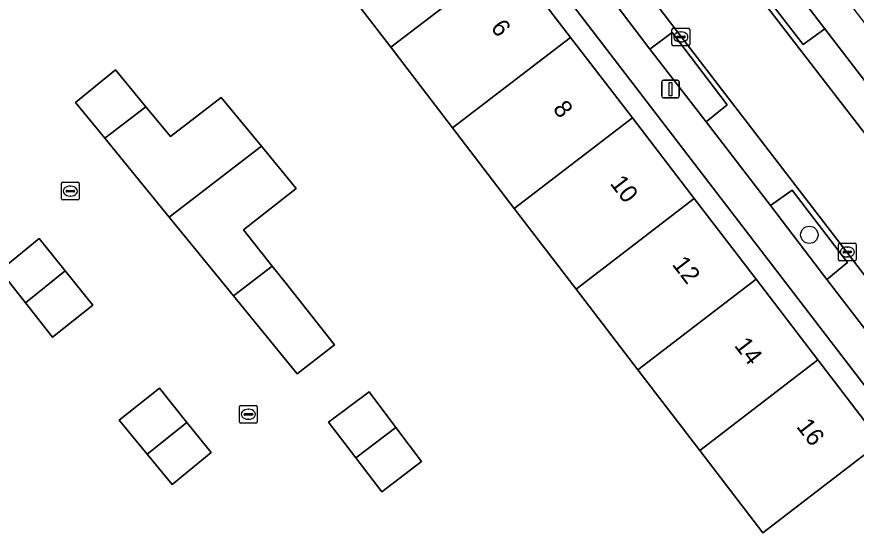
# Model space of a CAD drawing. Extents: x 161771 to 163125, y 382475 to 383179.
# Drawn here: x 162117.97 to 162165.3, y 382952.28 to 382981.52 of the extents above; entities that cross this region are included whole.
import ezdxf

# ---------------------------------------------------------------- set-up
doc = ezdxf.new("R2010")
doc.units = 0
for name, color, linetype in [('IMGEO_Boom', 7, 'Continuous'), ('IMGEO_Erf', 7, 'Continuous'), ('IMGEO_Groenvoorziening', 7, 'Continuous'), ('IMGEO_Kolk', 7, 'Continuous'), ('IMGEO_Lichtmast', 7, 'Continuous'), ('IMGEO_Pand', 7, 'Continuous'), ('IMGEO_Pand_nummerreeks', 7, 'Continuous'), ('IMGEO_Parkeervlak_open', 7, 'Continuous'), ('IMGEO_Rijbaan_lokaal_open', 7, 'Continuous'), ('IMGEO_Voetpad_open', 7, 'Continuous')]:
    doc.layers.add(name, color=color, linetype=linetype)

msp = doc.modelspace()

# ---------------------------------------------------------------- linework, layer by layer
at = {"layer": 'IMGEO_Boom'}
msp.add_circle((162162.658, 382969.221), 0.489, dxfattribs=at)
at = {"layer": 'IMGEO_Erf'}
for points in [[(162171.315, 382953.515), (162139.621, 382994.827)], [(162145.708, 382984.903), (162149.193, 382980.357), (162152.679, 382975.81), (162156.165, 382971.263), (162159.651, 382966.716), (162163.136, 382962.17), (162166.694, 382957.529), (162162.721, 382954.48), (162160.035, 382952.419), (162156.476, 382957.064), (162152.992, 382961.611), (162149.507, 382966.159), (162146.023, 382970.706), (162142.538, 382975.255), (162139.054, 382979.802), (162135.57, 382984.35)]]:
    msp.add_lwpolyline(points, dxfattribs=at)
for points in [[(162130.186, 382965.785), (162126.562, 382970.226), (162122.938, 382974.667), (162121.291, 382976.685), (162123.543, 382978.523), (162125.253, 382976.442), (162126.629, 382974.767), (162129.497, 382976.965), (162131.764, 382974.213), (162133.719, 382971.841), (162130.749, 382969.511), (162132.372, 382967.462), (162133.078, 382966.57), (162135.892, 382963.014), (162133.777, 382961.385)], [(162122.254, 382965.25), (162119.988, 382963.442), (162118.457, 382965.388), (162117.027, 382967.206), (162119.234, 382969.014), (162120.702, 382967.184)], [(162128.923, 382956.94), (162126.723, 382955.139), (162125.318, 382956.855), (162123.753, 382958.768), (162126.01, 382960.571), (162127.555, 382958.645)], [(162135.543, 382958.656), (162137.841, 382960.372), (162139.34, 382958.365), (162140.783, 382956.433), (162138.555, 382954.726), (162137.089, 382956.639)]]:
    msp.add_lwpolyline(points, close=True, dxfattribs=at)
at = {"layer": 'IMGEO_Groenvoorziening'}
for points in [[(162163.535, 382980.839), (162160.363, 382984.984), (162159.193, 382984.002), (162162.318, 382979.963)], [(162156.849, 382975.589), (162158.024, 382976.553), (162154.92, 382980.631), (162153.663, 382979.7)], [(162163.651, 382966.699), (162164.818, 382967.667), (162161.693, 382971.745), (162160.476, 382970.878)]]:
    msp.add_lwpolyline(points, close=True, dxfattribs=at)
at = {"layer": 'IMGEO_Kolk'}
for p, q in [((162154.912, 382979.955), (162154.912, 382980.807)), ((162154.987, 382980.881), (162155.839, 382980.881)), ((162155.913, 382980.807), (162155.913, 382979.955)), ((162155.171, 382980.375), (162155.171, 382980.387)), ((162155.609, 382980.338), (162155.211, 382980.338)), ((162155.214, 382980.424), (162155.612, 382980.424)), ((162155.4, 382980.661), (162155.425, 382980.661)), ((162155.655, 382980.387), (162155.655, 382980.375)), ((162155.839, 382979.881), (162154.987, 382979.881)), ((162155.423, 382980.101), (162155.398, 382980.101)), ((162120.492, 382971.26), (162120.492, 382972.112)), ((162120.567, 382972.186), (162121.419, 382972.186)), ((162120.98, 382971.966), (162121.005, 382971.966)), ((162121.493, 382972.112), (162121.493, 382971.26)), ((162120.751, 382971.68), (162120.751, 382971.692)), ((162121.189, 382971.643), (162120.791, 382971.643)), ((162120.794, 382971.729), (162121.192, 382971.729)), ((162121.003, 382971.406), (162120.978, 382971.406)), ((162121.235, 382971.692), (162121.235, 382971.68)), ((162121.419, 382971.186), (162120.567, 382971.186)), ((162164.299, 382967.828), (162164.299, 382968.68)), ((162164.374, 382968.754), (162165.226, 382968.754)), ((162164.787, 382968.534), (162164.812, 382968.534)), ((162165.3, 382968.68), (162165.3, 382967.828)), ((162164.558, 382968.248), (162164.558, 382968.26)), ((162164.996, 382968.211), (162164.598, 382968.211)), ((162164.601, 382968.297), (162164.999, 382968.297)), ((162165.042, 382968.26), (162165.042, 382968.248)), ((162165.226, 382967.754), (162164.374, 382967.754)), ((162164.81, 382967.974), (162164.785, 382967.974)), ((162130.529, 382958.676), (162130.529, 382959.528)), ((162130.604, 382959.602), (162131.456, 382959.602)), ((162131.53, 382959.528), (162131.53, 382958.676)), ((162130.788, 382959.096), (162130.788, 382959.108)), ((162131.226, 382959.059), (162130.828, 382959.059)), ((162130.831, 382959.145), (162131.229, 382959.145)), ((162131.017, 382959.382), (162131.042, 382959.382)), ((162131.272, 382959.108), (162131.272, 382959.096)), ((162131.456, 382958.602), (162130.604, 382958.602)), ((162131.04, 382958.822), (162131.015, 382958.822))]:
    msp.add_line(p, q, dxfattribs=at)
for points in [[(162154.912, 382979.955), (162154.912, 382980.807)], [(162154.987, 382980.881), (162155.839, 382980.881)], [(162155.913, 382980.807), (162155.913, 382979.955)], [(162155.839, 382979.881), (162154.987, 382979.881)], [(162120.492, 382971.26), (162120.492, 382972.112)], [(162120.567, 382972.186), (162121.419, 382972.186)], [(162121.493, 382972.112), (162121.493, 382971.26)], [(162121.419, 382971.186), (162120.567, 382971.186)], [(162164.299, 382967.828), (162164.299, 382968.68)], [(162164.374, 382968.754), (162165.226, 382968.754)], [(162165.3, 382968.68), (162165.3, 382967.828)], [(162165.226, 382967.754), (162164.374, 382967.754)], [(162130.529, 382958.676), (162130.529, 382959.528)], [(162130.604, 382959.602), (162131.456, 382959.602)], [(162131.53, 382959.528), (162131.53, 382958.676)], [(162131.456, 382958.602), (162130.604, 382958.602)]]:
    msp.add_lwpolyline(points, dxfattribs=at)
for centre, radius, start, end in [((162154.989, 382980.805), 0.0765, 91.552, 178.448), ((162154.989, 382980.805), 0.0765, 91.552, 178.448), ((162155.837, 382980.805), 0.0765, 1.552, 88.448), ((162155.837, 382980.805), 0.0765, 1.552, 88.448), ((162155.211, 382980.384), 0.0403, 85.8775, 175.7526), ((162155.208, 382980.374), 0.0366, 178.938, 274.7102), ((162155.612, 382980.381), 0.043, 264.8664, 352.4533), ((162155.616, 382980.386), 0.0386, 1.7309, 96.639), ((162154.989, 382979.957), 0.0765, 181.552, 268.448), ((162154.989, 382979.957), 0.0765, 181.552, 268.448), ((162155.837, 382979.957), 0.0765, 271.552, 358.448), ((162155.837, 382979.957), 0.0765, 271.552, 358.448), ((162120.569, 382972.11), 0.0765, 91.552, 178.448), ((162120.569, 382972.11), 0.0765, 91.552, 178.448), ((162121.417, 382972.11), 0.0765, 1.552, 88.448), ((162121.417, 382972.11), 0.0765, 1.552, 88.448), ((162120.791, 382971.689), 0.0403, 85.8775, 175.7526), ((162120.788, 382971.679), 0.0366, 178.938, 274.7102), ((162121.192, 382971.686), 0.043, 264.8664, 352.4533), ((162121.196, 382971.691), 0.0386, 1.7309, 96.639), ((162120.569, 382971.262), 0.0765, 181.552, 268.448), ((162120.569, 382971.262), 0.0765, 181.552, 268.448), ((162121.417, 382971.262), 0.0765, 271.552, 358.448), ((162121.417, 382971.262), 0.0765, 271.552, 358.448), ((162164.376, 382968.678), 0.0765, 91.552, 178.448), ((162164.376, 382968.678), 0.0765, 91.552, 178.448), ((162165.224, 382968.678), 0.0765, 1.552, 88.448), ((162165.224, 382968.678), 0.0765, 1.552, 88.448), ((162164.598, 382968.257), 0.0403, 85.8775, 175.7526), ((162164.595, 382968.247), 0.0366, 178.938, 274.7102), ((162164.999, 382968.254), 0.043, 264.8664, 352.4533), ((162165.003, 382968.259), 0.0386, 1.7309, 96.639), ((162164.376, 382967.83), 0.0765, 181.552, 268.448), ((162164.376, 382967.83), 0.0765, 181.552, 268.448), ((162165.224, 382967.83), 0.0765, 271.552, 358.448), ((162165.224, 382967.83), 0.0765, 271.552, 358.448), ((162130.606, 382959.526), 0.0765, 91.552, 178.448), ((162130.606, 382959.526), 0.0765, 91.552, 178.448), ((162131.454, 382959.526), 0.0765, 1.552, 88.448), ((162131.454, 382959.526), 0.0765, 1.552, 88.448), ((162130.828, 382959.105), 0.0403, 85.8775, 175.7526), ((162130.825, 382959.095), 0.0366, 178.938, 274.7102), ((162131.229, 382959.102), 0.043, 264.8664, 352.4533), ((162131.233, 382959.107), 0.0386, 1.7309, 96.639), ((162130.606, 382958.678), 0.0765, 181.552, 268.448), ((162130.606, 382958.678), 0.0765, 181.552, 268.448), ((162131.454, 382958.678), 0.0765, 271.552, 358.448), ((162131.454, 382958.678), 0.0765, 271.552, 358.448)]:
    msp.add_arc(centre, radius, start, end, dxfattribs=at)
for centre, major_axis, ratio, start_param, end_param in [((162155.399, 382980.381), (-0.387, 0.002), 0.722429, 4.712389, 7.853982), ((162155.424, 382980.381), (-0.39, 0.002), 0.717154, 1.570796, 4.712389), ((162120.979, 382971.686), (-0.387, 0.002), 0.722429, 4.712389, 7.853982), ((162121.004, 382971.686), (-0.39, 0.002), 0.717154, 1.570796, 4.712389), ((162164.786, 382968.254), (-0.387, 0.002), 0.722429, 4.712389, 7.853982), ((162164.811, 382968.254), (-0.39, 0.002), 0.717154, 1.570796, 4.712389), ((162131.016, 382959.102), (-0.387, 0.002), 0.722429, 4.712389, 7.853982), ((162131.041, 382959.102), (-0.39, 0.002), 0.717154, 1.570796, 4.712389)]:
    msp.add_ellipse(centre, major_axis=major_axis, ratio=ratio, start_param=start_param, end_param=end_param, dxfattribs=at)
at = {"layer": 'IMGEO_Lichtmast'}
for p, q in [((162154.437, 382977.94), (162155.227, 382977.94)), ((162155.227, 382977.94), (162154.437, 382977.94)), ((162154.337, 382977.04), (162154.337, 382977.84)), ((162154.337, 382977.84), (162154.337, 382977.04)), ((162155.327, 382977.84), (162155.327, 382977.04)), ((162155.327, 382977.04), (162155.327, 382977.84)), ((162155.227, 382976.94), (162154.437, 382976.94)), ((162154.437, 382976.94), (162155.227, 382976.94))]:
    msp.add_line(p, q, dxfattribs=at)
msp.add_lwpolyline([(162154.757, 382977.815), (162154.907, 382977.815), (162154.907, 382977.065), (162154.757, 382977.065), (162154.757, 382977.815)], dxfattribs=at)
for centre, start, end in [((162154.437, 382977.84), 90, 180), ((162154.437, 382977.84), 90, 180), ((162155.227, 382977.84), 0, 90), ((162155.227, 382977.84), 360, 90), ((162154.437, 382977.04), 180, 270), ((162154.437, 382977.04), 180, 270), ((162155.227, 382977.04), 270, 0), ((162155.227, 382977.04), 270, 0)]:
    msp.add_arc(centre, 0.1, start, end, dxfattribs=at)
at = {"layer": 'IMGEO_Pand'}
for points in [[(162135.57, 382984.35), (162139.054, 382979.802), (162145.708, 382984.903), (162142.222, 382989.449)], [(162142.538, 382975.255), (162149.193, 382980.357), (162145.708, 382984.903), (162139.054, 382979.802)], [(162146.023, 382970.706), (162152.679, 382975.81), (162149.193, 382980.357), (162142.538, 382975.255)], [(162122.938, 382974.667), (162125.253, 382976.442), (162123.543, 382978.523), (162121.291, 382976.685)], [(162122.938, 382974.667), (162126.562, 382970.226), (162131.764, 382974.213), (162129.497, 382976.965), (162126.629, 382974.767), (162125.253, 382976.442)], [(162146.023, 382970.706), (162149.507, 382966.159), (162156.165, 382971.263), (162152.679, 382975.81)], [(162132.372, 382967.462), (162130.749, 382969.511), (162133.719, 382971.841), (162131.764, 382974.213), (162126.562, 382970.226), (162130.186, 382965.785)], [(162152.992, 382961.611), (162159.651, 382966.716), (162156.165, 382971.263), (162149.507, 382966.159)], [(162118.457, 382965.388), (162120.702, 382967.184), (162119.234, 382969.014), (162117.027, 382967.206)], [(162118.457, 382965.388), (162119.988, 382963.442), (162122.254, 382965.25), (162120.702, 382967.184)], [(162133.078, 382966.57), (162132.372, 382967.462), (162130.186, 382965.785), (162133.777, 382961.385), (162135.892, 382963.014)], [(162152.992, 382961.611), (162156.476, 382957.064), (162163.136, 382962.17), (162159.651, 382966.716)], [(162163.136, 382962.17), (162156.476, 382957.064), (162160.035, 382952.419), (162162.721, 382954.48), (162166.694, 382957.529)], [(162127.555, 382958.645), (162126.01, 382960.571), (162123.753, 382958.768), (162125.318, 382956.855)], [(162137.089, 382956.639), (162139.34, 382958.365), (162137.841, 382960.372), (162135.543, 382958.656)], [(162128.923, 382956.94), (162127.555, 382958.645), (162125.318, 382956.855), (162126.723, 382955.139)], [(162139.34, 382958.365), (162137.089, 382956.639), (162138.555, 382954.726), (162140.783, 382956.433)]]:
    msp.add_lwpolyline(points, close=True, dxfattribs=at)
at = {"layer": 'IMGEO_Parkeervlak_open'}
for points in [[(162167.192, 382976.055), (162163.535, 382980.839), (162162.318, 382979.963), (162159.193, 382984.002), (162160.363, 382984.984), (162156.714, 382989.742), (162155.504, 382988.842), (162152.377, 382992.935), (162153.571, 382993.887), (162149.938, 382998.592), (162148.529, 382997.562), (162149.973, 382995.579), (162159.297, 382983.356), (162168.797, 382971.042)], [(162186.675, 382939.645), (162164.967, 382967.99), (162155.587, 382980.205), (162146.1, 382992.584), (162144.637, 382994.482), (162143.255, 382993.387), (162146.898, 382988.568), (162148.065, 382989.499), (162151.214, 382985.379), (162150.047, 382984.472), (162153.663, 382979.7), (162154.92, 382980.631), (162158.024, 382976.553), (162156.849, 382975.589), (162160.476, 382970.878), (162161.693, 382971.745), (162164.818, 382967.667), (162163.651, 382966.699), (162167.291, 382961.958)]]:
    msp.add_lwpolyline(points, dxfattribs=at)
at = {"layer": 'IMGEO_Rijbaan_lokaal_open'}
msp.add_lwpolyline([(162190.52, 382942.548), (162179.444, 382957.091), (162168.797, 382971.042), (162159.297, 382983.356), (162149.973, 382995.579), (162148.529, 382997.562), (162146.663, 383000), (162143.611, 383003.987), (162134.174, 383016.299), (162129.47, 383022.481), (162125.524, 383019.408), (162130.182, 383013.35), (162139.638, 383000.986), (162140.396, 383000), (162144.637, 382994.482), (162146.1, 382992.584), (162155.587, 382980.205), (162164.967, 382967.99), (162186.675, 382939.645), (162187.025, 382939.151), (162190.892, 382942.041)], close=True, dxfattribs=at)
at = {"layer": 'IMGEO_Voetpad_open'}
for points in [[(162179.375, 382963.431), (162151.372, 383000), (162149.412, 383002.56), (162148.596, 383003.625), (162147.19, 383002.547), (162145.715, 383004.453), (162140.87, 383010.86), (162133.689, 383020.164), (162133.469, 383020.47), (162131.042, 383023.652), (162129.47, 383022.481), (162134.174, 383016.299), (162143.611, 383003.987), (162146.663, 383000), (162148.529, 382997.562), (162149.938, 382998.592), (162153.571, 382993.887), (162156.714, 382989.742), (162160.363, 382984.984), (162163.535, 382980.839), (162167.192, 382976.055)], [(162167.291, 382961.958), (162163.651, 382966.699), (162160.476, 382970.878), (162156.849, 382975.589), (162153.663, 382979.7), (162150.047, 382984.472), (162146.898, 382988.568), (162143.255, 382993.387), (162144.637, 382994.482), (162140.396, 383000), (162139.638, 383000.986), (162130.182, 383013.35), (162125.524, 383019.408), (162123.942, 383018.171), (162126.366, 383015.06), (162126.609, 383014.749), (162133.74, 383005.493), (162138.654, 382999.011), (162140.12, 382997.098), (162138.709, 382996.016), (162139.621, 382994.827), (162171.315, 382953.515)]]:
    msp.add_lwpolyline(points, dxfattribs=at)

# ---------------------------------------------------------------- texts
at = {"layer": 'IMGEO_Pand_nummerreeks'}
for s, p in [('6', (162144.652, 382980.889)), ('8', (162148.158, 382976.315)), ('10', (162151.382, 382972.111)), ('12', (162154.882, 382967.546)), ('14', (162158.388, 382962.973)), ('16', (162161.892, 382958.403))]:
    msp.add_text(s, height=1, rotation=307.4756, dxfattribs=at).set_placement(p)

doc.saveas('drawing.dxf')
